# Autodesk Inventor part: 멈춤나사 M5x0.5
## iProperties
Company: 한국ATC센터
IsCustomPart: 1
Created: 2014-11
Part Number: 멈춤나사 M5x0.5
Material: 강, 연강
Description: 6각 소켓 머리 없는 멈춤 나사
Document SubType Name: Modeling
Standard: KS B 1028
Designer: KYOUNG IL JANG
Standards Organization: KS
Language: ko-KR
Size Designation: 원추점 M5x10
Categories: <MemberInstance><Categories><Category DisplayName="조임쇠" InternalName="e4da775c-781d-43d5-af7c-5136215cf5a6" Mnemonic="FSTN"><Category DisplayName="볼트" InternalN
Density: 7.86 g/cm^3
Mass: 1.16912 g
Surface Area: 1.91683 cm^2
Volume: 0.148743 cm^3
Author: KYOUNG IL JANG
